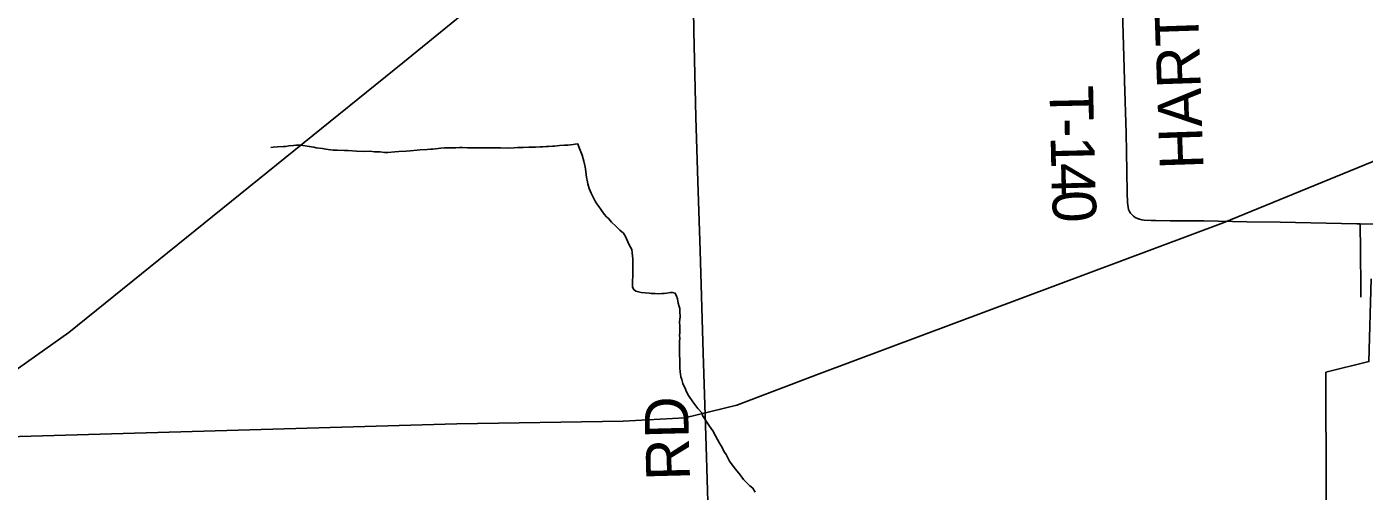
# Model space of a CAD drawing. Extents: x -12 to 34, y 0 to 22.
# Drawn here: x 4.257 to 5.999, y 16.758 to 17.363 of the extents above; entities that cross this region are included whole.
import ezdxf

# ---------------------------------------------------------------- set-up
doc = ezdxf.new("R2010")
doc.units = 0
for name, color, linetype in [('GM_X_Corporation', 7, 'Continuous'), ('GM_X_County_Road_Text', 7, 'Continuous'), ('GM_X_Major_River', 7, 'Continuous'), ('GM_X_Minor_Lake', 7, 'Continuous')]:
    doc.layers.add(name, color=color, linetype=linetype)

msp = doc.modelspace()

# ---------------------------------------------------------------- linework, layer by layer
at = {"layer": 'GM_X_Corporation'}
for points in [[(4.2152, 16.8961), (4.3122, 16.9647), (4.7469, 17.316), (5.0381, 17.5535), (5.1871, 17.6698), (5.6595, 18.0409), (6.0545, 18.3551), (6.0978, 18.3867), (6.1312, 18.4021), (6.1695, 18.4095), (6.5535, 18.4423), (6.6901, 18.4479), (6.8503, 18.4485), (6.9294, 18.4522), (7.1075, 18.4541), (7.2559, 18.4584), (7.2861, 18.4516), (7.3783, 18.4473), (7.7344, 18.4572)], [(4.008, 16.8225), (4.8175, 16.8457), (5.034, 16.8494), (5.1143, 16.8539), (5.182, 16.8703), (5.2892, 16.9112), (5.8151, 17.1077), (6.2198, 17.2736)]]:
    msp.add_lwpolyline(points, dxfattribs=at)
at = {"layer": 'GM_X_Major_River'}
for points in [[(5.6861, 17.3095), (5.6834, 17.3983), (5.6817, 17.4481), (5.68, 17.4948), (5.6762, 17.613), (5.6739, 17.672), (5.6714, 17.7153), (5.6707, 17.7233), (5.6703, 17.728), (5.6702, 17.7315), (5.6704, 17.7351), (5.6708, 17.7384)], [(5.1259, 17.3593), (5.1237, 17.4816), (5.1222, 17.557), (5.1218, 17.6065), (5.1219, 17.6097), (5.1223, 17.6125), (5.1231, 17.6147), (5.1241, 17.6162), (5.1259, 17.6178), (5.1289, 17.6196)], [(5.1602, 16.0968), (5.16, 16.1056), (5.1598, 16.1212), (5.1514, 16.4598), (5.1467, 16.6399), (5.1444, 16.73), (5.1419, 16.817), (5.1379, 16.9381), (5.134, 17.0716), (5.1312, 17.1617), (5.1286, 17.2455), (5.126, 17.3573), (5.1259, 17.3593)], [(5.6959, 17.1184), (5.6943, 17.1204), (5.693, 17.1225), (5.6919, 17.1252), (5.6912, 17.1281), (5.6905, 17.1342), (5.6901, 17.1466), (5.6896, 17.1746), (5.6886, 17.2249), (5.6866, 17.2926), (5.6861, 17.3095)], [(5.7272, 17.1107), (5.7212, 17.1108), (5.712, 17.1113), (5.709, 17.1117), (5.7061, 17.1124), (5.7033, 17.1134), (5.7006, 17.1148), (5.6981, 17.1164), (5.6959, 17.1184)], [(5.9933, 17.1065), (5.9888, 17.1066), (5.8892, 17.1085), (5.8457, 17.1092), (5.7897, 17.1103), (5.7461, 17.1105), (5.7272, 17.1107)], [(6.1356, 17.1039), (6.1257, 17.1041), (6.0386, 17.1059), (5.9933, 17.1065)], [(5.9941, 17.011), (5.994, 17.0359), (5.9937, 17.0577), (5.9936, 17.0764), (5.9933, 17.1013), (5.9933, 17.1065)]]:
    msp.add_lwpolyline(points, dxfattribs=at)
at = {"layer": 'GM_X_Minor_Lake'}
for points in [[(4.5752, 17.206), (4.5783, 17.2064), (4.584, 17.2068), (4.5916, 17.2072), (4.5946, 17.2072), (4.5988, 17.208), (4.6048, 17.2084), (4.6079, 17.2088), (4.6139, 17.2088), (4.617, 17.2084), (4.6227, 17.2077), (4.6253, 17.2073), (4.631, 17.2062), (4.6341, 17.2055), (4.6424, 17.2044), (4.647, 17.2036), (4.6565, 17.2025), (4.6614, 17.2022), (4.6709, 17.2018), (4.6759, 17.2019), (4.6865, 17.2012), (4.6956, 17.2008), (4.7043, 17.2009), (4.71, 17.2001), (4.7176, 17.2002), (4.7233, 17.1994), (4.7275, 17.1994), (4.7366, 17.2002), (4.7419, 17.2007), (4.7514, 17.2011), (4.7564, 17.2015), (4.7655, 17.2023), (4.7696, 17.2027), (4.7787, 17.2031), (4.7829, 17.2035), (4.786, 17.2039), (4.7966, 17.2051), (4.8011, 17.2055), (4.8159, 17.2056), (4.8209, 17.206), (4.8247, 17.206), (4.8311, 17.2056), (4.8345, 17.2056), (4.8418, 17.2053), (4.874, 17.2054), (4.8839, 17.2051), (4.8919, 17.2055), (4.8961, 17.2059), (4.9036, 17.206), (4.9109, 17.2064), (4.9196, 17.2064), (4.9257, 17.2068), (4.9291, 17.2068), (4.9336, 17.2072), (4.9367, 17.2073), (4.942, 17.2077), (4.9446, 17.2077), (4.9481, 17.2081), (4.9511, 17.2085), (4.9575, 17.2089), (4.9617, 17.2089), (4.9686, 17.2097), (4.9712, 17.2101), (4.975, 17.2105), (4.9762, 17.2067), (4.9777, 17.2025), (4.9804, 17.1957), (4.9827, 17.1881), (4.9843, 17.1805), (4.9851, 17.1744), (4.9855, 17.1706), (4.9862, 17.1668), (4.987, 17.1634), (4.9878, 17.1585), (4.9897, 17.1524), (4.992, 17.1463), (4.9947, 17.141), (4.9974, 17.1361), (4.9997, 17.1323), (5.002, 17.1289), (5.0054, 17.1247), (5.0093, 17.119), (5.0123, 17.1156), (5.0154, 17.113), (5.0188, 17.1084), (5.0241, 17.1035), (5.0295, 17.0982), (5.0341, 17.0944), (5.0371, 17.0899), (5.0413, 17.08), (5.0433, 17.0759), (5.0452, 17.0728), (5.0456, 17.0686), (5.0464, 17.061), (5.0465, 17.039), (5.0458, 17.0314), (5.0458, 17.0272), (5.0458, 17.0238), (5.0477, 17.0208), (5.0504, 17.0189), (5.0572, 17.017)], [(6.0078, 17.0347), (6.0046, 16.9271), (5.9488, 16.9132), (5.9497, 16.4438), (5.8464, 16.4406), (6.1125, 16.4487)], [(5.0572, 17.017), (5.0675, 17.0159), (5.0705, 17.0155), (5.0755, 17.0156), (5.08, 17.0152), (5.0842, 17.0156), (5.0872, 17.0156), (5.0906, 17.016), (5.0956, 17.0168), (5.0982, 17.0168), (5.1017, 17.0161), (5.1032, 17.0123), (5.1044, 17.0089), (5.1055, 17.0032), (5.1067, 16.9986), (5.1075, 16.996), (5.1075, 16.9918), (5.1079, 16.9857), (5.1072, 16.9785), (5.1076, 16.9732), (5.1076, 16.9655), (5.1073, 16.9606), (5.1076, 16.9579), (5.1073, 16.9522), (5.1073, 16.9462), (5.1075, 16.9188), (5.1079, 16.9135), (5.1083, 16.9108), (5.109, 16.907), (5.1102, 16.9036), (5.1117, 16.8983), (5.1148, 16.8911), (5.116, 16.8884), (5.119, 16.8827), (5.1244, 16.8744), (5.1309, 16.8657), (5.1366, 16.86), (5.137, 16.8566), (5.1462, 16.843), (5.1504, 16.8369), (5.1542, 16.8301), (5.1592, 16.8206), (5.1615, 16.8172), (5.1657, 16.8088), (5.168, 16.8058), (5.1722, 16.7971), (5.1745, 16.7941), (5.1799, 16.7869), (5.186, 16.7793), (5.1906, 16.7736), (5.1933, 16.7706), (5.1986, 16.7653), (5.2028, 16.7619), (5.2059, 16.757)]]:
    msp.add_lwpolyline(points, dxfattribs=at)

# ---------------------------------------------------------------- texts
at = {"layer": 'GM_X_County_Road_Text'}
for s, height, rotation, p in [('HARTSHORN RD', 0.056818, 91.9446, (5.7894, 17.1783)), ('T', 0.0568, 271.2344, (5.5888, 17.2862)), ('-', 0.0568, 271.2521, (5.5897, 17.2437)), ('1', 0.0568, 271.2742, (5.5903, 17.2203)), ('4', 0.0568, 271.4746, (5.591, 17.1851)), ('0', 0.0568, 272.6114, (5.592, 17.1489)), ('RD', 0.05682, 91.4844, (5.1209, 16.7727))]:
    msp.add_text(s, height=height, rotation=rotation, dxfattribs=at).set_placement(p)

doc.saveas('drawing.dxf')
